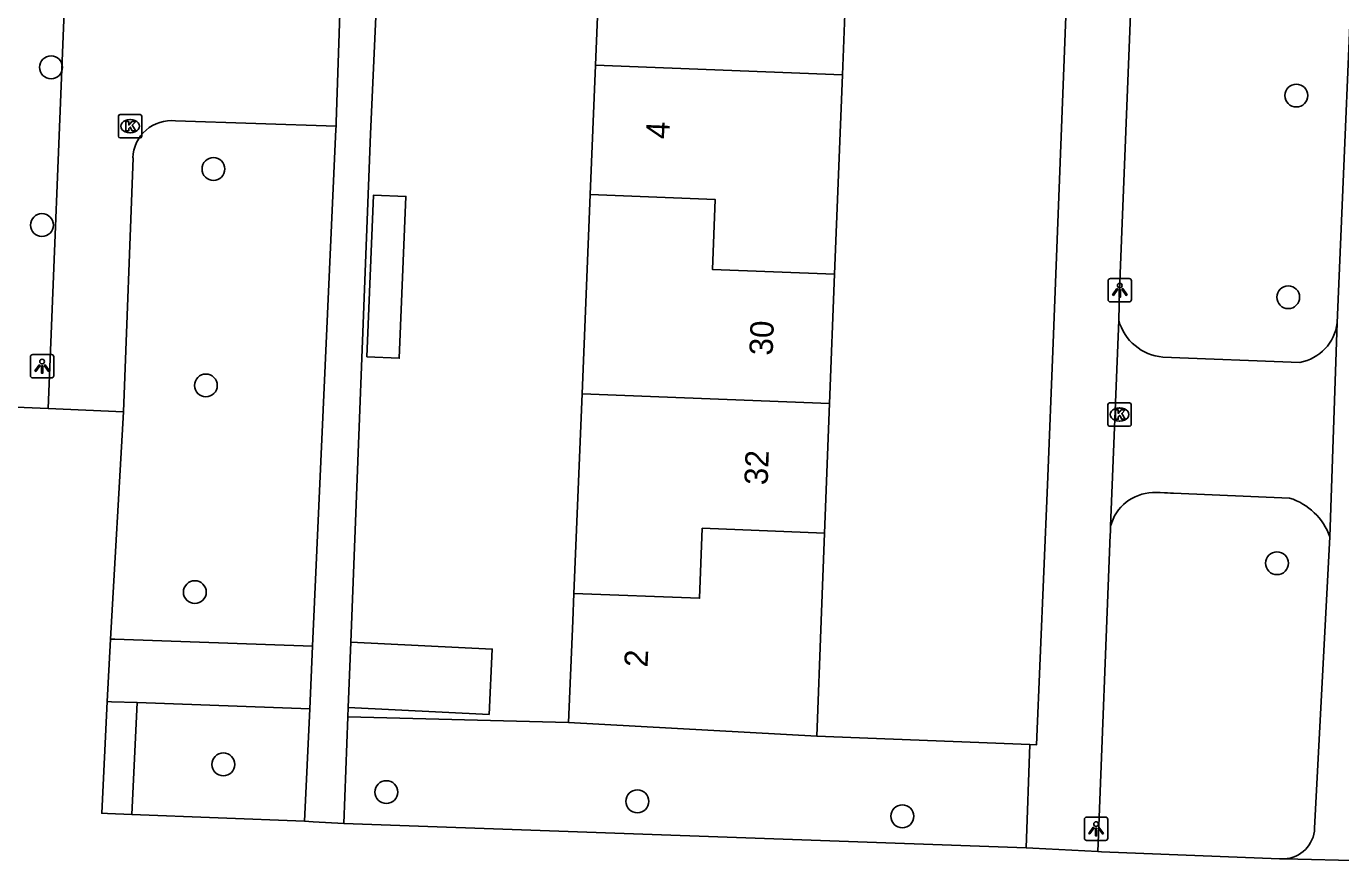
# Model space of a CAD drawing. Extents: x 160787 to 161428, y 386828 to 387483.
# Drawn here: x 161236.6 to 161292.9, y 386989.7 to 387025.4 of the extents above; entities that cross this region are included whole.
import ezdxf

# ---------------------------------------------------------------- set-up
doc = ezdxf.new("R2010")
doc.units = 0
for name, color, linetype in [('IMGEO_Boom', 7, 'Continuous'), ('IMGEO_Groenvoorziening', 7, 'Continuous'), ('IMGEO_Kolk', 7, 'Continuous'), ('IMGEO_Lichtpunt', 7, 'Continuous'), ('IMGEO_Muur', 7, 'Continuous'), ('IMGEO_Pand', 7, 'Continuous'), ('IMGEO_Pand_nummerreeks', 7, 'Continuous'), ('IMGEO_Rijbaan_lokaal_open', 7, 'Continuous'), ('IMGEO_Voetpad_open', 7, 'Continuous')]:
    doc.layers.add(name, color=color, linetype=linetype)

msp = doc.modelspace()

# ---------------------------------------------------------------- linework, layer by layer
at = {"layer": 'IMGEO_Boom'}
for centre in [(161237.677, 387023.693), (161291.02, 387022.484), (161244.633, 387019.342), (161237.286, 387016.94), (161290.673, 387013.853), (161244.309, 387010.076), (161290.19, 387002.467), (161243.835, 387001.229), (161245.057, 386993.855), (161252.039, 386992.67), (161262.792, 386992.274), (161274.142, 386991.636)]:
    msp.add_circle(centre, 0.489, dxfattribs=at)
at = {"layer": 'IMGEO_Groenvoorziening'}
for points in [[(161250.394, 386995.886), (161259.849, 386995.65)], [(161279.6, 386994.71), (161270.474, 386995.066)]]:
    msp.add_lwpolyline(points, dxfattribs=at)
at = {"layer": 'IMGEO_Kolk'}
for p, q in [((161240.564, 387020.747), (161240.564, 387021.599)), ((161240.639, 387021.673), (161241.491, 387021.673)), ((161241.052, 387021.453), (161241.077, 387021.453)), ((161241.565, 387021.599), (161241.565, 387020.747)), ((161241.491, 387020.673), (161240.639, 387020.673)), ((161241.075, 387020.893), (161241.05, 387020.893)), ((161283.021, 387009.331), (161283.873, 387009.331)), ((161282.946, 387008.405), (161282.946, 387009.257)), ((161283.434, 387009.111), (161283.459, 387009.111)), ((161283.947, 387009.257), (161283.947, 387008.405)), ((161283.873, 387008.331), (161283.021, 387008.331)), ((161283.457, 387008.551), (161283.432, 387008.551))]:
    msp.add_line(p, q, dxfattribs=at)
for points in [[(161240.564, 387020.747), (161240.564, 387021.599)], [(161240.639, 387021.673), (161241.491, 387021.673)], [(161240.885, 387021.373), (161241.008, 387021.373), (161241.008, 387021.222), (161241.138, 387021.373), (161241.302, 387021.373), (161241.156, 387021.222), (161241.309, 387020.973), (161241.157, 387020.973), (161241.072, 387021.137), (161241.008, 387021.07), (161241.008, 387020.973), (161240.885, 387020.973), (161240.885, 387021.373)], [(161241.565, 387021.599), (161241.565, 387020.747)], [(161241.491, 387020.673), (161240.639, 387020.673)], [(161283.021, 387009.331), (161283.873, 387009.331)], [(161282.946, 387008.405), (161282.946, 387009.257)], [(161283.267, 387009.031), (161283.39, 387009.031), (161283.39, 387008.88), (161283.52, 387009.031), (161283.684, 387009.031), (161283.538, 387008.88), (161283.691, 387008.631), (161283.539, 387008.631), (161283.454, 387008.795), (161283.39, 387008.728), (161283.39, 387008.631), (161283.267, 387008.631), (161283.267, 387009.031)], [(161283.947, 387009.257), (161283.947, 387008.405)], [(161283.873, 387008.331), (161283.021, 387008.331)]]:
    msp.add_lwpolyline(points, dxfattribs=at)
for centre, start, end in [((161240.641, 387021.597), 91.552, 178.448), ((161240.641, 387021.597), 91.552, 178.448), ((161241.489, 387021.597), 1.552, 88.448), ((161241.489, 387021.597), 1.552, 88.448), ((161240.641, 387020.749), 181.552, 268.448), ((161240.641, 387020.749), 181.552, 268.448), ((161241.489, 387020.749), 271.552, 358.448), ((161241.489, 387020.749), 271.552, 358.448), ((161283.023, 387009.255), 91.552, 178.448), ((161283.023, 387009.255), 91.552, 178.448), ((161283.871, 387009.255), 1.552, 88.448), ((161283.871, 387009.255), 1.552, 88.448), ((161283.023, 387008.407), 181.552, 268.448), ((161283.023, 387008.407), 181.552, 268.448), ((161283.871, 387008.407), 271.552, 358.448), ((161283.871, 387008.407), 271.552, 358.448)]:
    msp.add_arc(centre, 0.0765, start, end, dxfattribs=at)
for centre, major_axis, ratio, start_param, end_param in [((161241.051, 387021.173), (-0.387, 0.002), 0.722429, 4.712389, 7.853982), ((161241.076, 387021.173), (-0.39, 0.002), 0.717154, 1.570796, 4.712389), ((161283.433, 387008.831), (-0.387, 0.002), 0.722429, 4.712389, 7.853982), ((161283.458, 387008.831), (-0.39, 0.002), 0.717154, 1.570796, 4.712389)]:
    msp.add_ellipse(centre, major_axis=major_axis, ratio=ratio, start_param=start_param, end_param=end_param, dxfattribs=at)
at = {"layer": 'IMGEO_Lichtpunt'}
for p, q in [((161282.958, 387014.556), (161282.958, 387013.749)), ((161282.958, 387014.556), (161282.958, 387013.749)), ((161283.86, 387014.651), (161283.052, 387014.651)), ((161283.86, 387014.651), (161283.052, 387014.651)), ((161283.954, 387013.749), (161283.954, 387014.556)), ((161283.954, 387013.749), (161283.954, 387014.556)), ((161283.052, 387013.655), (161283.86, 387013.655)), ((161283.052, 387013.655), (161283.86, 387013.655)), ((161236.795, 387011.301), (161236.795, 387010.494)), ((161236.795, 387011.301), (161236.795, 387010.494)), ((161237.697, 387011.396), (161236.889, 387011.396)), ((161237.697, 387011.396), (161236.889, 387011.396)), ((161237.791, 387010.494), (161237.791, 387011.301)), ((161237.791, 387010.494), (161237.791, 387011.301)), ((161236.889, 387010.4), (161237.697, 387010.4)), ((161236.889, 387010.4), (161237.697, 387010.4)), ((161281.942, 386991.504), (161281.942, 386990.697)), ((161281.942, 386991.504), (161281.942, 386990.697)), ((161282.844, 386991.599), (161282.036, 386991.599)), ((161282.844, 386991.599), (161282.036, 386991.599)), ((161282.938, 386990.697), (161282.938, 386991.504)), ((161282.938, 386990.697), (161282.938, 386991.504)), ((161282.036, 386990.603), (161282.844, 386990.603)), ((161282.036, 386990.603), (161282.844, 386990.603))]:
    msp.add_line(p, q, dxfattribs=at)
for points in [[(161283.332, 387014.22), (161283.371, 387014.192), (161283.183, 387013.93), (161283.145, 387013.957), (161283.332, 387014.22)], [(161283.434, 387014.172), (161283.481, 387014.172), (161283.481, 387013.85), (161283.434, 387013.85), (161283.434, 387014.172)], [(161283.544, 387014.192), (161283.582, 387014.219), (161283.769, 387013.957), (161283.73, 387013.929), (161283.544, 387014.192)], [(161237.169, 387010.965), (161237.208, 387010.937), (161237.02, 387010.675), (161236.982, 387010.702), (161237.169, 387010.965)], [(161237.271, 387010.917), (161237.318, 387010.917), (161237.318, 387010.595), (161237.271, 387010.595), (161237.271, 387010.917)], [(161237.381, 387010.937), (161237.419, 387010.964), (161237.606, 387010.702), (161237.567, 387010.674), (161237.381, 387010.937)], [(161282.316, 386991.168), (161282.355, 386991.14), (161282.167, 386990.878), (161282.129, 386990.905), (161282.316, 386991.168)], [(161282.418, 386991.12), (161282.465, 386991.12), (161282.465, 386990.798), (161282.418, 386990.798), (161282.418, 386991.12)], [(161282.528, 386991.14), (161282.566, 386991.167), (161282.753, 386990.905), (161282.714, 386990.877), (161282.528, 386991.14)]]:
    msp.add_lwpolyline(points, dxfattribs=at)
for centre in [(161283.457, 387014.354), (161237.294, 387011.099), (161282.441, 386991.302)]:
    msp.add_circle(centre, 0.0994, dxfattribs=at)
for centre, start, end in [((161283.052, 387014.556), 90, 180), ((161283.052, 387014.556), 90, 180), ((161283.86, 387014.556), 0, 90), ((161283.86, 387014.556), 0, 90), ((161283.052, 387013.749), 180, 270), ((161283.052, 387013.749), 180, 270), ((161283.86, 387013.749), 270, 0), ((161283.86, 387013.749), 270, 360), ((161236.889, 387011.301), 90, 180), ((161236.889, 387011.301), 90, 180), ((161237.697, 387011.301), 0, 90), ((161237.697, 387011.301), 0, 90), ((161236.889, 387010.494), 180, 270), ((161236.889, 387010.494), 180, 270), ((161237.697, 387010.494), 270, 0), ((161237.697, 387010.494), 270, 360), ((161282.036, 386991.504), 90, 180), ((161282.036, 386991.504), 90, 180), ((161282.844, 386991.504), 0, 90), ((161282.844, 386991.504), 0, 90), ((161282.036, 386990.697), 180, 270), ((161282.036, 386990.697), 180, 270), ((161282.844, 386990.697), 270, 0), ((161282.844, 386990.697), 270, 360)]:
    msp.add_arc(centre, 0.0946, start, end, dxfattribs=at)
at = {"layer": 'IMGEO_Muur'}
for points in [[(161281.457, 387033.987), (161280.607, 387011.897)], [(161250.518, 386999.088), (161251.362, 387020.829)], [(161279.893, 386994.699), (161280.357, 387005.827)], [(161250.394, 386995.886), (161250.41, 386996.289)], [(161259.849, 386995.65), (161250.394, 386995.886)]]:
    msp.add_lwpolyline(points, dxfattribs=at)
at = {"layer": 'IMGEO_Pand'}
for points in [[(161271.905, 387031.917), (161271.574, 387023.378)], [(161261.004, 387023.789), (161261.232, 387029.33)], [(161260.777, 387018.249), (161261.004, 387023.789)], [(161261.004, 387023.789), (161271.574, 387023.378)], [(161271.574, 387023.378), (161271.242, 387014.841)], [(161251.207, 387011.3), (161252.594, 387011.243), (161252.878, 387018.167), (161251.491, 387018.224), (161251.207, 387011.3)], [(161260.427, 387009.712), (161260.777, 387018.249)], [(161271.242, 387014.841), (161266.005, 387015.044), (161266.121, 387018.041), (161260.777, 387018.249)], [(161271.242, 387014.841), (161271.027, 387009.3)], [(161260.076, 387001.174), (161260.427, 387009.712)], [(161271.027, 387009.3), (161260.427, 387009.712)], [(161271.027, 387009.3), (161270.812, 387003.758)], [(161270.812, 387003.758), (161265.574, 387003.961), (161265.458, 387000.964), (161260.076, 387001.174)], [(161270.812, 387003.758), (161270.666, 387000), (161270.474, 386995.066)], [(161259.849, 386995.65), (161260.028, 387000), (161260.076, 387001.174)], [(161250.518, 386999.088), (161256.573, 386998.795), (161256.438, 386995.998), (161250.41, 386996.289)], [(161250.41, 386996.289), (161250.518, 386999.088)], [(161270.474, 386995.066), (161259.849, 386995.65)]]:
    msp.add_lwpolyline(points, dxfattribs=at)
at = {"layer": 'IMGEO_Rijbaan_lokaal_open'}
for points in [[(161239.655, 387061.146), (161237.546, 387009.09)], [(161250.087, 387027.277), (161249.889, 387021.346), (161249.884, 387021.17)], [(161243.002, 387021.399), (161249.884, 387021.17)], [(161240.778, 387008.953), (161241.187, 387019.813)], [(161235.161, 387009.191), (161237.546, 387009.09)], [(161237.546, 387009.09), (161240.778, 387008.953)], [(161240.778, 387008.953), (161240.221, 386999.223)], [(161240.221, 386999.223), (161240.087, 386996.55)], [(161240.087, 386996.55), (161239.846, 386991.763), (161240.096, 386991.753), (161241.131, 386991.712)], [(161241.131, 386991.712), (161248.536, 386991.419)], [(161248.536, 386991.419), (161248.91, 386991.404), (161250.219, 386991.326)], [(161250.219, 386991.326), (161279.442, 386990.286)], [(161279.442, 386990.286), (161279.738, 386990.275), (161282.51, 386990.128)], [(161282.51, 386990.128), (161282.675, 386990.119), (161290.302, 386989.816), (161290.499, 386989.812)], [(161290.499, 386989.812), (161293.996, 386989.734)]]:
    msp.add_lwpolyline(points, dxfattribs=at)
msp.add_arc((161242.819, 387019.777), 1.633, 83.5676, 178.7282, dxfattribs=at)
at = {"layer": 'IMGEO_Voetpad_open'}
for points in [[(161282.648, 387065.39), (161282.55, 387062.294), (161281.713, 387040.195), (161281.457, 387033.987), (161280.607, 387011.897), (161280.357, 387005.827), (161279.893, 386994.699), (161279.6, 386994.71)], [(161252.609, 387052.1), (161252.488, 387049.164), (161251.638, 387026.827), (161251.362, 387020.829), (161250.518, 386999.088)], [(161283.413, 387012.864), (161283.451, 387014.153), (161284.157, 387032.058)], [(161292.771, 387012.758), (161293.577, 387031.886)], [(161249.884, 387021.17), (161249.879, 387021.039), (161248.876, 386998.916)], [(161283.063, 387004.058), (161283.413, 387012.864)], [(161292.459, 387003.6), (161292.771, 387012.758)], [(161285.304, 387011.288), (161291.17, 387011.058)], [(161284.863, 387005.487), (161284.992, 387005.49), (161285.12, 387005.49), (161285.192, 387005.489), (161285.374, 387005.483), (161285.501, 387005.477), (161285.627, 387005.47), (161285.753, 387005.463), (161290.733, 387005.255)], [(161282.51, 386990.128), (161283.049, 387003.683), (161283.054, 387003.808), (161283.059, 387003.934), (161283.063, 387004.058)], [(161291.803, 386991.13), (161292.459, 387003.6)], [(161240.221, 386999.223), (161240.413, 386999.216), (161248.876, 386998.916)], [(161248.876, 386998.916), (161248.755, 386996.238)], [(161241.372, 386996.5), (161240.259, 386996.54), (161240.087, 386996.55)], [(161241.131, 386991.712), (161241.372, 386996.5)], [(161248.755, 386996.238), (161241.372, 386996.5)], [(161248.755, 386996.238), (161248.536, 386991.419)], [(161250.219, 386991.326), (161250.394, 386995.886)], [(161250.41, 386996.289), (161250.394, 386995.886)], [(161279.6, 386994.71), (161279.442, 386990.286)]]:
    msp.add_lwpolyline(points, dxfattribs=at)
for centre, radius, start, end in [((161285.491, 387013.435), 2.155, 195.3699, 265.013), ((161290.801, 387013.01), 1.986, 280.7181, 352.7176), ((161284.913, 387003.576), 1.912, 91.5067, 165.3846), ((161289.923, 387002.683), 2.696, 19.8811, 72.525), ((161290.432, 386991.182), 1.372, 272.7968, 357.8151)]:
    msp.add_arc(centre, radius, start, end, dxfattribs=at)

# ---------------------------------------------------------------- texts
at = {"layer": 'IMGEO_Pand_nummerreeks'}
for s, rotation, p in [('4', 87.6498, (161264.156, 387020.61)), ('30', 87.7769, (161268.585, 387011.346)), ('32', 87.7769, (161268.37, 387005.798)), ('2', 87.6468, (161263.229, 386998.002))]:
    msp.add_text(s, height=1, rotation=rotation, dxfattribs=at).set_placement(p)

doc.saveas('drawing.dxf')
